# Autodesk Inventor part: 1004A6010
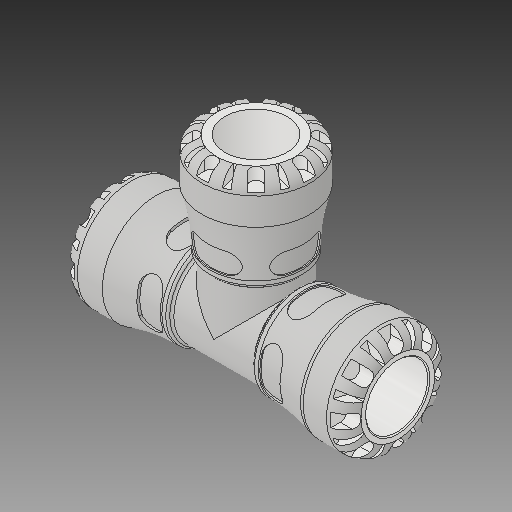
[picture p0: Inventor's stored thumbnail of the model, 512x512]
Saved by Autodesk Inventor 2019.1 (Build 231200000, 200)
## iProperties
Created: 2016-12
Part Number: 1004A6010
Material: Generic
Description: PLASSON TEE 1''IPS SERIES 1
Document SubType Name: Modeling
Designer: KIM
Mass: 664.223 g
Surface Area: 733.008 cm^2
Volume: 474.445 cm^3
Density: 1 g/cm^3
Appearance: Default
Author: KIM
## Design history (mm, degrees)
derived "1004A6.ipt"
feature "Solid1::1004A6.ipt"
tag "TaggingFeature1"
body "Solid1"
other parameters: "d_" = 33.3, "E_" = 57.912, "l_" = 53.848, "A_" = 83.82, "H_" = 151.892, "d9" = 9.2295, "d11" = 57.912, "d12" = 39.453, "d230" = 57.912, "d231" = 41.625, "d232" = 8.1435, "d1" = 22.61616, "d2" = 33.3, "d3" = 39.453, "d4" = 57.912, "d8" = 49.2252, "d13" = 7.3836, "d14" = 7.3836, "d15" = 0, "d17" = 360 deg, "d19" = 8 deg, "d20" = 0.666, "d21" = 0.666, "d22" = 8 deg, "d24" = 0, "d26" = 360 deg, "d33" = 5.7912, "d43" = 45.17136, "d51" = 0.57912, "d54" = 11.655, "d55" = 7.326, "d57" = 12.76901, "d58" = 0, "d74" = 0, "d78" = 53.848, "d79" = 45.17136, "d80" = 151.892, "d82" = 0.666, "d115" = 360 deg, "d139" = 7.3836, "d140" = 0, "d142" = 360 deg, "d207" = 90 deg, "d209" = 22.61616, "d210" = 33.3, "d211" = 41.625, "d212" = 57.912, "d213" = 49.2252, "d215" = 45.17136, "d216" = 2.775, "d217" = 53.848, "d225" = 83.82, "d226" = 53.848, "d228" = 9.90675, "d229" = 6.5148, "d233" = 6.5148, "d234" = 0, "d236" = 360 deg, "d238" = 8 deg, "d239" = 8 deg, "d240" = 0.666, "d241" = 0.666, "d243" = 0, "d245" = 360 deg, "d247" = 1.15824, "d248" = 3.23088, "d249" = 3.23088, "d250" = 9.90675, "d252" = 11.655, "d253" = 7.659, "d254" = 12.76901, "d255" = 0, "d257" = 360 deg, "d259" = 0.666, "d261" = 0, "d262" = 1.15824, "d264" = 0, "d266" = 0, "d268" = 26.64
